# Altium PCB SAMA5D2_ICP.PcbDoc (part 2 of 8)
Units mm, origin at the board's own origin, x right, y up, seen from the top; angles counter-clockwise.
Board outline 150 x 100 mm, 6 copper layers (L1 - TOP, L2 - GND, L3 - SIG, L4 - SIG, L5 - VCC, L6 - BOT), stack 1.512 mm thick; 708 components, 597 nets, 2710 pads, 1437 vias.
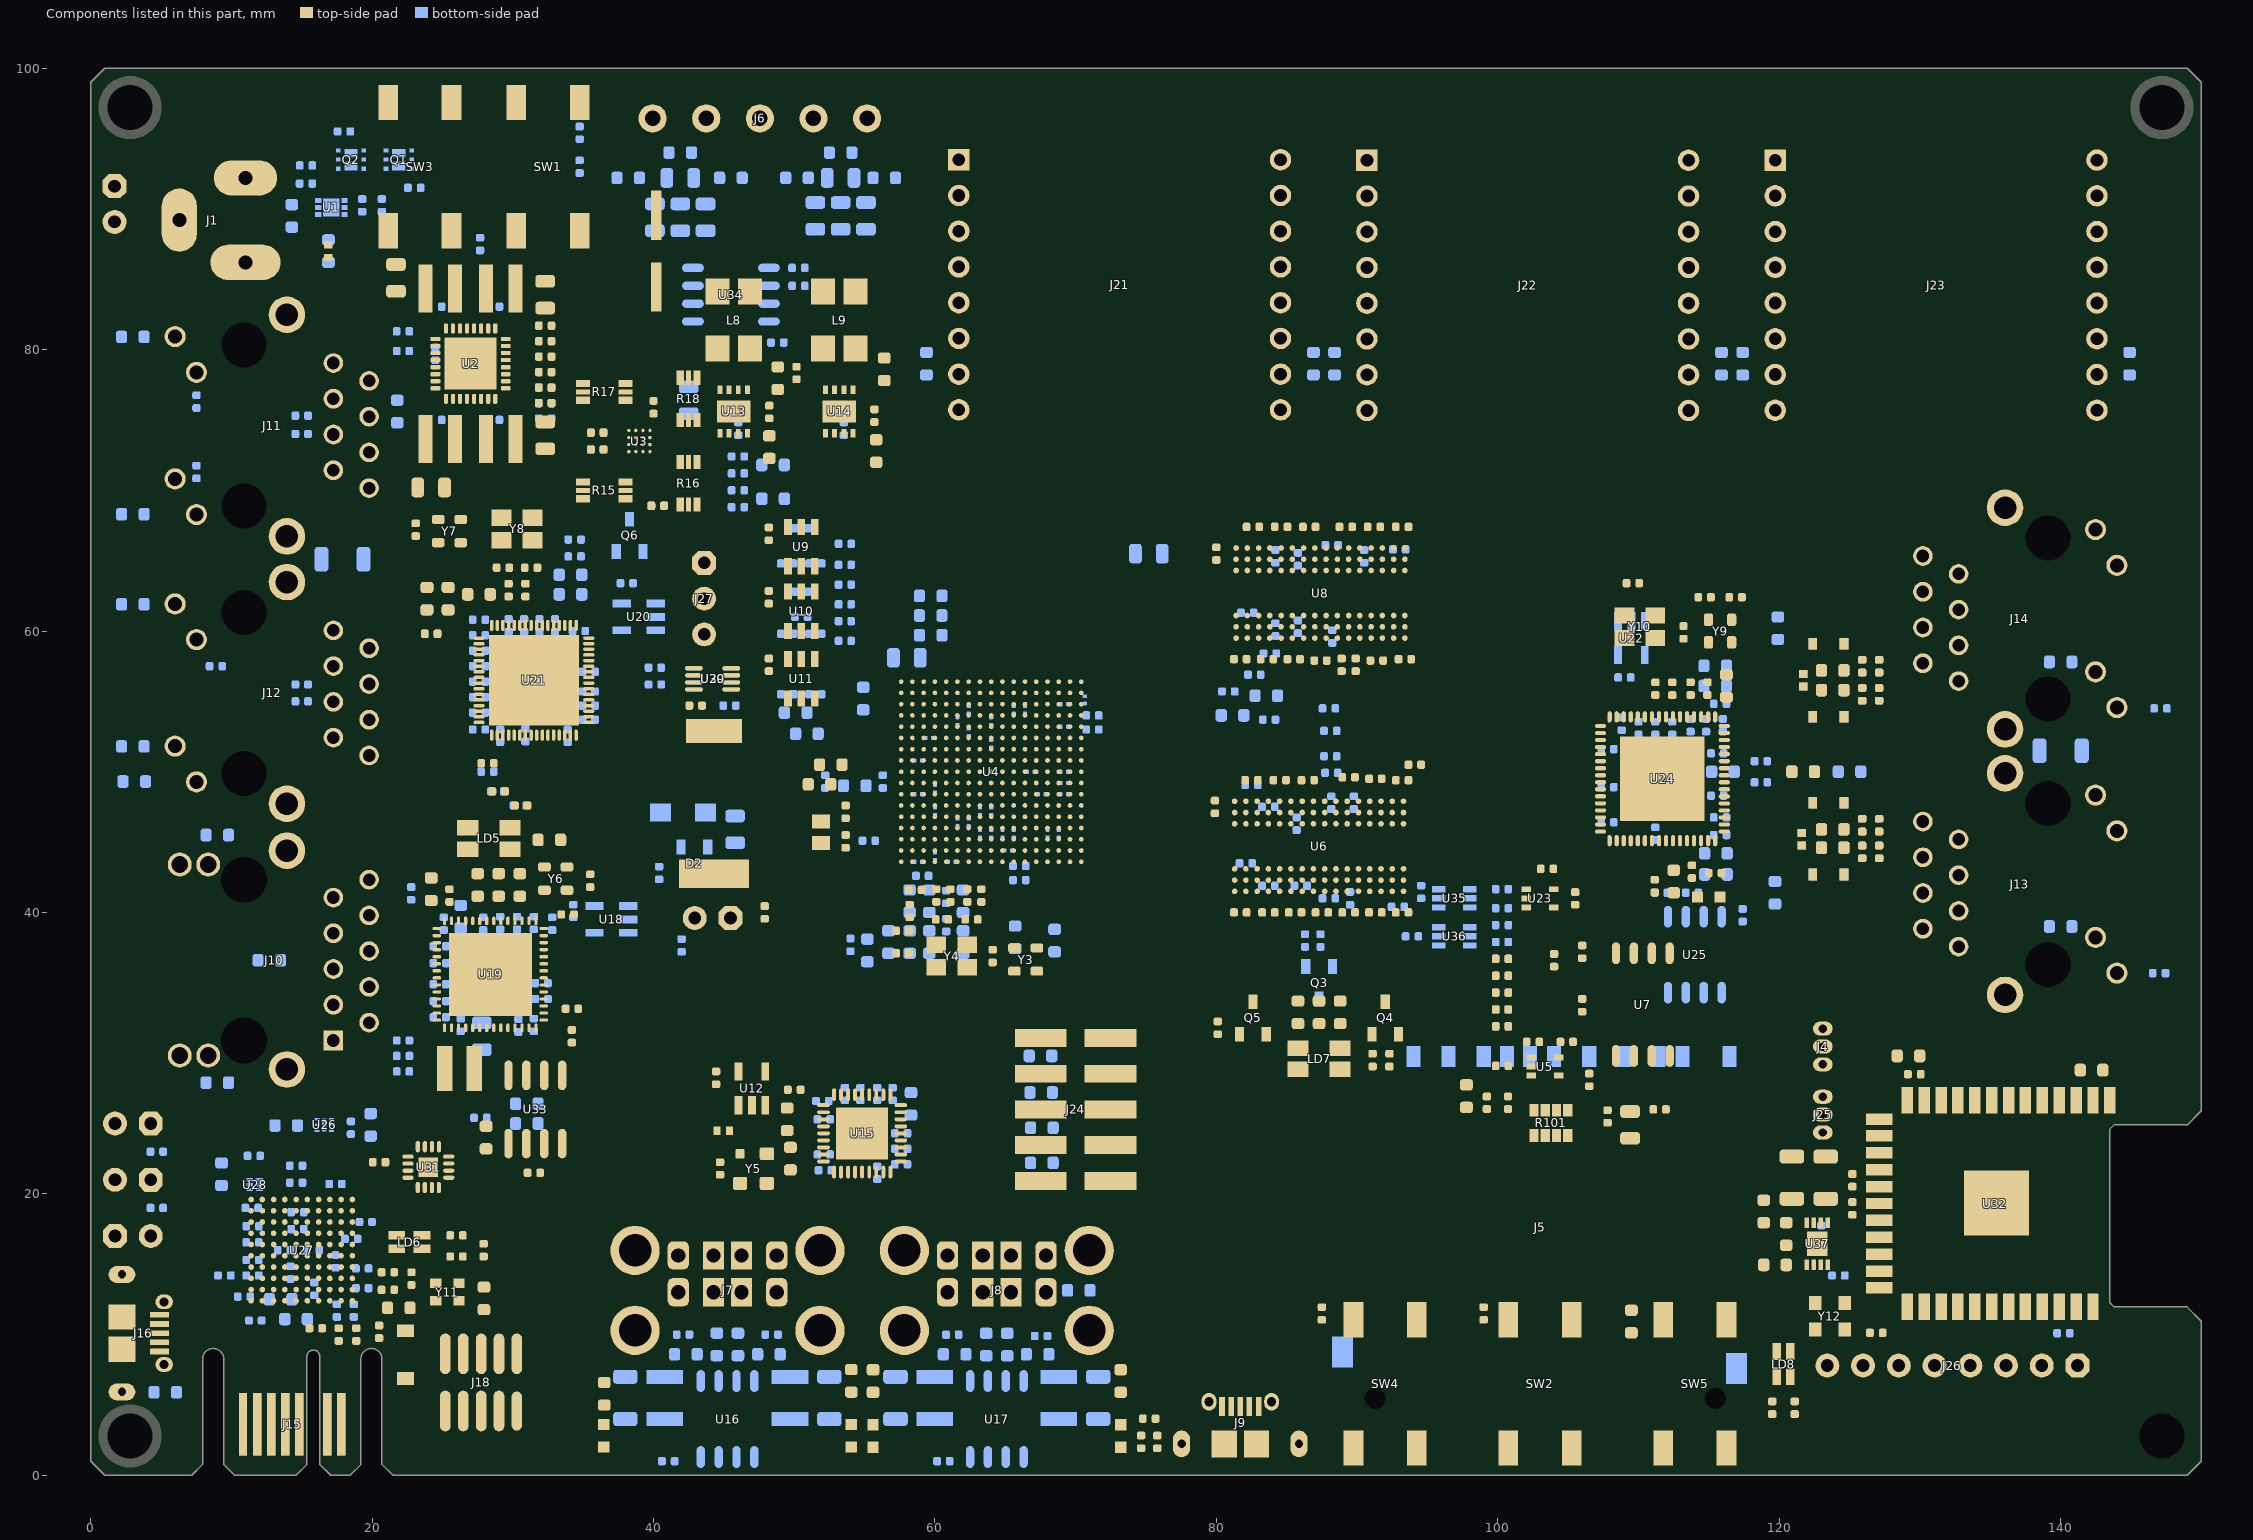
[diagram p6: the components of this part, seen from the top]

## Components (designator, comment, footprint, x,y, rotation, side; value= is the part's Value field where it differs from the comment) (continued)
R191 "Resistor" RES_C_0603 123.8,55.8 r180 top value=0R
R192 "Resistor" RES_C_0603 123.8,57.2 r180 top value=0R
R193 "Resistor" RES_C_0402 127.1,55.5 r270 bottom value=49.9R
R194 "Resistor" RES_C_0402 127.1,44.3 r270 top value=49.9R
R195 "Resistor" RES_C_0402 127.1,57.5 r90 bottom value=49.9R
R197 "Resistor" RES_C_0402 127.1,55.5 r270 top value=49.9R
R198 "Resistor" RES_C_1206 140,51.5 r180 bottom value=0R
R199 "Resistor" RES_C_0402 18.875,10 r270 top value=10k
R200 "Resistor" RES_C_0402 16,10.45 r180 top value=100R
R201 "Resistor" RES_C_0402 17.625,10 r90 top value=100R
R202 "Resistor" RES_C_0603 21.9,11.9 r180 top value=51R
R203 "Resistor" RES_C_0402 19.3,14.7 r0 bottom value=39R
R204 "Resistor" RES_C_0402 19.3,13.3 r0 bottom value=39R
R205 "Resistor" RES_C_0402 11.5,14.2 r0 bottom value=0R
R206 "Resistor" RES_C_0402 21.125,13.175 r180 top value=6.8k
R207 "Resistor" RES_C_0402 11.5,15.3 r0 bottom value=100k
R208 "Resistor" RES_C_0402 27.925,16 r270 top value=10k
R209 "Resistor" RES_C_0603 27.95,12.575 r90 top value=0R
R210 "Resistor" RES_C_0402 25.21,9 r90 bottom value=100R
R211 "Resistor" RES_C_0402 30.265,4.9 r270 bottom value=100k
R212 "Resistor" RES_C_0402 28.99,4.9 r270 bottom value=100k
R213 "Resistor" RES_C_0402 26.44,4.9 r270 bottom value=100k
R214 "Resistor" RES_C_0402 11.45,19 r0 bottom value=220R
R215 "Resistor" RES_C_0402 11.5,17.7 r0 bottom value=150R
R216 "Resistor" RES_C_0603 9.3,21.4 r270 bottom value=1k
R217 "Resistor" RES_C_0402 4.7,23 r0 bottom value=10k
R218 "Resistor" RES_C_0402 26,17.05 r0 top value=100R
R219 "Resistor" RES_C_0402 22.8,13.975 r270 top value=100R
R220 "Resistor" RES_C_0402 4.7,19 r0 bottom value=10k
R221 "Resistor" RES_C_0402 14.7,18.7 r0 bottom value=150R
R222 "Resistor" RES_C_0402 14.6,22 r0 bottom value=150R
R223 "Resistor" RES_C_0402 14.6,20.8 r180 bottom value=150R
R224 "Resistor" RES_C_0603 67.6,20.8 r0 bottom value=330R
R225 "Resistor" RES_C_0603 67.6,23.5 r0 bottom value=330R
R226 "Resistor" RES_C_0603 67.55,26 r0 bottom value=330R
R227 "Resistor" RES_C_0603 67.55,28.5 r180 bottom value=0R
R228 "Resistor" RES_C_0603 67.5,31.1 r180 bottom value=0R
R229 "Resistor" RES_C_0603 59.4,79 r270 bottom value=0R
R230 "Resistor" RES_C_0603 88.4,79 r270 bottom value=0R
R231 "Resistor" RES_C_0603 117.4,79 r270 bottom value=0R
R232 "Resistor" RES_C_0603 67.6,22.2 r180 bottom value=330R
R233 "Resistor" RES_C_0603 67.6,24.7 r180 bottom value=330R
R234 "Resistor" RES_C_0603 67.55,27.2 r180 bottom value=0R
R235 "Resistor" RES_C_0603 67.5,29.8 r0 bottom value=0R
R236 "Resistor" RES_C_0603 86.9,79 r270 bottom value=0R
R237 "Resistor" RES_C_0603 115.9,79 r270 bottom value=0R
R238 "Resistor" RES_C_0603 144.9,79 r270 bottom value=0R
R239 "Resistor" RES_C_0402 86.3,38 r270 bottom value=100R
R240 "Resistor" RES_C_0402 91.1,29.5 r90 top value=100R
R241 "Resistor" RES_C_0402 80.1,31.8 r270 top value=100R
R242 "Resistor" RES_C_0402 87.4,38 r90 bottom value=10k
R243 "Resistor" RES_C_0402 92.3,29.5 r270 top value=10k
R244 "Resistor" RES_C_0603 87.3,32.9 r270 top value=1k
R245 "Resistor" RES_C_0603 88.8,32.9 r270 top value=1k
R246 "Resistor" RES_C_0603 85.8,32.9 r270 top value=2.2k
R247 "Resistor" RES_C_0402 125.2,18.965 r90 top value=100k
R248 "Resistor" RES_C_0603 142.2,28.8 r0 top value=0R
R249 "Resistor" RES_C_0402 140.2,10.1 r0 bottom value=10k
R250 "Resistor" RES_C_0402 34.75,93 r90 bottom value=100R
R251 "Resistor" RES_C_0402 99,11.5 r270 top value=100R
R252 "Resistor" RES_C_0402 27.675,87.5 r90 bottom value=100R
R254 "Resistor" RES_C_0402 87.5,11.5 r270 top value=100R
R255 "Resistor" RES_C_0603 109.5,10.925 r90 top value=0R
R256 "Resistor" RES_C_0402 34.75,95.4 r90 bottom value=10k
R257 "Resistor" RES_C_0402 121.1,4.8 r270 top value=100R
R258 "Resistor" RES_C_0402 119.5,4.8 r270 top value=100R
R259 "Resistor" RES_C_0402 30.5,47.6 r180 bottom value=4.7k
R260 "Resistor" RES_C_0402 127.1,57.5 r90 top value=49.9R
R261 "Resistor" RES_C_0402 147,35.69 r180 bottom value=10k
R262 "Resistor" RES_C_0402 147.1,54.5 r180 bottom value=10k
R263 "Resistor" RES_C_0402 7.52,71.3 r90 bottom value=10k
R264 "Resistor" RES_C_0402 7.52,76.3 r270 bottom value=10k
R265 "Resistor" RES_C_0402 8.9,57.5 r0 bottom value=10k
R266 "Resistor" RES_C_0402 28.2,50.6 r180 top value=4.7k
R267 "Resistor" RES_C_0402 30.6,47.6 r180 top value=4.7k
R268 "Resistor" RES_C_0402 42,37.65 r270 bottom value=10k
R269 "Resistor" RES_C_0402 50.3,85.805 r180 bottom value=22R
R270 "Resistor" RES_C_0402 50.3,84.535 r180 bottom value=22R
R271 "Resistor" RES_C_0402 124.2,14.2 r180 bottom value=10k
SW1 "Switch 4 Pin" SW_SMD_6mmX6mm_TL3301 32.5,93 r270 top locked value="TACT SPST"
SW2 "Switch 4 Pin" SW_SMD_6mmX6mm_TL3301 103,6.5 r90 top value="TACT SPST"
SW3 "Switch 4 Pin" SW_SMD_6mmX6mm_TL3301 23.4,93 r270 top locked value="TACT SPST"
SW4 "Switch 4 Pin" SW_SMD_6mmX6mm_TL3301 92,6.5 r90 top value="TACT SPST"
SW5 "Switch 4 Pin" SW_SMD_6mmX6mm_TL3301 114,6.5 r90 top value="TACT SPST"
U1 "NCP349 DFN-6" DFN-6_2x1.6_EP0.4x0.35 17.1,90.1 r90 bottom value=NCP349MNAETBG
U2 "MCP16502AA" QFN-32_5X5_EP3.7X3.7 27,79 r0 top
U3 "PAC1934 WLCSP-16" WLCSP-16_2.215X2.16 39,73.5 r180 top value=PAC1934
U4 "ATSAMA5D27C LFBGA-289" LFBGA-289_P0.8_14x14x1.4 64,50 r0 top locked value=ATSAMA5D27C
U5 "NL17SZ126-D SOT-353" SOT-353 103.355,29.05 r270 top value=NL17SZ126-D
U6 "W632GU6MB" TFBGA-96_13X7.5 87.3,44.7 r90 top locked value=W632GU6MB-12
U7 "SST26VFXXX SOIC-8_WSON-8_SOIJ-8" SOIJ-8 110.305,33.45 r90 top value=SST26VF064B
U8 "W632GU6MB" TFBGA-96_13X7.5 87.4,62.7 r90 top locked value=W632GU6MB-12
U9 "24XXXX SOT-23-6" SOT-23-6 50.5,66 r0 top value=24AA025E48
U10 "24XXXX SOT-23-6" SOT-23-6 50.5,61.4 r0 top value=24AA025E48
U11 "24XXXX SOT-23-6" SOT-23-6 50.5,56.6 r0 top value=24AA025E48
U12 "74XX1G08_9 SOT-23-5" SOT-23-5 46.995,27.5 r0 top value=SN74LVC1G08DBVR
U13 "MCP2542 DFN-8" DFN-8_3x3_EP2.4X1.55 45.7,75.6 r0 top value=MCP2542
U14 "MCP2542 DFN-8" DFN-8_3x3_EP2.4X1.55 53.2,75.6 r0 top value=MCP2542
U15 "USB2534 SQFN-36" QFN-36_6x6_EP3.7x3.7 54.83,24.3 r90 top locked value=USB2534I-1080AEN
U16 "MIC2026-2076 DIP-8 SOIC-8" SOIC-8 45.265,4 r90 bottom value=MIC2026-1YM
U17 "MIC2026-2076 DIP-8 SOIC-8" SOIC-8 64.4,4 r90 bottom value=MIC2026-1YM
U18 "74XX1G08_9 SOT-23-5" SOT-23-5 37,39.5 r270 bottom value=SN74LVC1G08DBVR
U19 "LAN7850 QFN-56" QFN-56_8X8_EP5.9X5.9 28.4,35.6 r0 top value=LAN7850T
U20 "74XX1G08_9 SOT-23-5" SOT-23-5 38.95,61 r270 bottom value=SN74LVC1G08DBVR
U21 "KSZ8563RNX" QFN-64_8X8-EP6.5SQ 31.5,56.5 r0 top locked
U22 "74XX1G08_9 SOT-23-5" SOT-23-5 109.5,59.5 r0 bottom value=SN74LVC1G08DBVR
U23 "NL17SZ125-D SOT-353" SOT-353 103,41 r270 top value=NL17SZ125-D
U24 "LAN9252 QFN-64" QFN-64_9X9_EP6 111.7,49.5 r270 top locked value=LAN9252I/ML
U25 "24XX01_02_04_08_16_32_64_128_256_512_1025 SOIC-8_SOIJ-8_TSSOP-8_PDIP-8_MSOP-8" SOIC-8 114,37 r90 bottom value=24FC512
U26 "MIC5528MT DFN-6" DFN-6_1.2x1.2 16.6,24.9 r270 bottom value="MIC5528 3V3"
U27 "ATSAM3U4CA-CU TFBGA-100" TFBGA-100_P0.8_9X9X1.1 15,16 r180 top value=ATSAM3U4CA-CU
U28 "NLAS3157 ULLGA-6" ULLGA-6_1X1 11.65,20.65 r270 bottom value=NLAS3157MX3TC
U29 "NL27WZ125 US-8" US-8 44.2,56.6 r0 bottom value=NL27WZ125USG
U30 "NL27WZ126 US-8" US-8 44.2,56.6 r180 top value=NL27WZ126USG
U31 "NLAS3899B QFN16" QFN-16_3X3_EP1.4X1.4 24,21.9 r90 top value=NLAS3899B
U32 "MODULE ATWILC3000-MR110CA" "MODULE ATWILC3000-MR110CA" 135.45,19.345 r270 top value=ATWILC3000-MR110CA
U33 "93XX66A_B_C PDIP-8_SOIC-8_TSSOP-8_MSOP-8" SOIC-8_150MIL 31.6,26 r270 top value=93AA66A
U34 "ATECC608A-SSHDA-B SOIC-8" SOIC-8 45.5,83.9 r0 bottom value=ATECC608A-SSHDA
U35 "74LVC1G3157 SOT-23-6_SC-70-6" SC-70-6 96.896,41 r270 bottom value=74LVC1G3157
U36 "74LVC1G3157 SOT-23-6_SC-70-6" SC-70-6 96.9,38.3 r270 bottom value=74LVC1G3157
U37 "MCP172X FIX DFN-8" DFN-8_2x3 122.7,16.45 r0 top value=MCP1725/3.3V
Y1 "Crystal 2 Pins" CRYSTAL_NX2012SA 51.9,45.7 r270 top value=32.768kHz
Y3 "DSC10xx DFN-4" DFN-4_2.5x2 66.446,36.652 r90 top value=12MHz
Y4 "Crystal 4 pins 1-3" CRYSTAL_TSX-3225_L3.2W2.5H0.6 61.2,36.9 r180 top value=12Mhz
Y5 "DSC10xx DFN-4" CDFN-4_3.2X2.5 47.103,21.796 r0 top value=24MHz
Y6 "DSC10xx DFN-4" DFN-4_2.5x2 33.05,42.405 r90 top value=25MHz
Y7 "DSC10xx DFN-4" DFN-4_2.5x2 25.5,67.1 r270 top value=25MHz
Y8 "Crystal 4 pins 1-3" CRYSTAL_L3.2W2.5H0.8 30.3,67.25 r0 top value=25MHz
Y9 "DSC10xx DFN-4" DFN-4_2.5x2 115.8,60 r180 top value=25MHz
Y10 "Crystal 4 pins 1-3" CRYSTAL_L3.2W2.5H0.8 110.1,60.3 r180 top value=25MHz
Y11 "OSCILLATOR DSC60XX" OSCILLATOR_DSC60000L2.5W2.0H0.89 25.35,13.025 r180 top value="12.00 MHz"
Y12 "OSC_DSC6083CE2A_3225" OSCILLATOR_DSC1001_L3.2W2.5H0.85 123.6,11.3 r180 top value=32.768Hz

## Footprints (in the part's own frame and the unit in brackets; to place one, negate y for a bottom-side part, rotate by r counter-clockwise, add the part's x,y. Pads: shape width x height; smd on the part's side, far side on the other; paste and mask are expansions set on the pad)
10067847-001RLF [mm]
  rect 1x1.5 smd: 1(6.475,12.15) 2(3.975,12.15) 3(0.675,12.15) 4(-1.025,12.15) 5(-3.525,12.15) 6(-6.025,12.15) 7(-8.45,12.15) 8(-10.15,12.15) 9(8.975,12.15) 10(2.325,12.15) 11(-13.5,12.15)
  round 0 hole 1.5 unplated mask+0.05: 1.5mm(-12.5,-12.15) 1.5mm(11.7,-12.15)
  rect 1.5x2.2 smd: 12(-14,-10.05) 12(14,-8.85)
  L1 - TOP keep-out region: 8.425,3.05 9.525,3.05 9.525,1.05 8.425,1.05
  L1 - TOP keep-out region: 0.55,5.25 2.45,5.25 2.45,2.75 0.55,2.75
  L1 - TOP keep-out region: 5.925,6.05 7.025,6.05 7.025,3.55 5.925,3.55
  L1 - TOP keep-out region: 3.425,5.25 4.525,5.25 4.525,3.25 3.425,3.25
  L1 - TOP keep-out region: -1.575,4.75 -0.475,4.75 -0.475,2.75 -1.575,2.75
  L1 - TOP keep-out region: -4.075,5.15 -2.975,5.15 -2.975,3.15 -4.075,3.15
  L1 - TOP keep-out region: -6.575,5.15 -5.475,5.15 -5.475,3.15 -6.575,3.15
  L1 - TOP keep-out region: -15.1,2.35 -13.9,2.35 -13.9,-3.95 -15.1,-3.95
  L1 - TOP keep-out region: -9,5.15 -7.9,5.15 -7.9,3.15 -9,3.15
  L1 - TOP keep-out region: -10.7,5.15 -9.6,5.15 -9.6,3.15 -10.7,3.15
  silkscreen extent -15,-17.85 15,13.15, body extent -14.23,-17.65 14.22,12.6, height 2.9
CAP_AL_D8 [mm]
  rect 3.5x0.75 smd: 1(-2.55,0) 2(2.55,0)
  silkscreen extent -3.43,-3.3 3.43,3.3, body extent -3.5,-3.3 3.5,3.3, height 7.7
CAP_C_0201 [mm] "Chip Capacitor, 2-Leads, Body 0.6x0.3mm, IPC Medium Density"
  rrect50% 0.275x0.3 smd mask+0.064: 1(-0.262,0) 2(0.262,0)
  body extent -0.3,-0.15 0.3,0.15, height 0.28
CAP_C_0402 [mm] "Chip Capacitor, 2-Leads, Body 1.0x0.5mm, IPC High Density"
  rrect50% 0.55x0.6 smd: 1(-0.45,0) 2(0.45,0)
  body extent -0.5,-0.3 0.5,0.3, height 0.2
CAP_C_0603 [mm] "Chip Capacitor, 2-Leads, Body 1.6x0.8mm, IPC Medium Density"
  rrect50% 0.8x0.9 smd: 1(-0.8,0) 2(0.8,0)
  silkscreen extent -0.1,-0.38 0.1,0.38, body extent -0.8,-0.4 0.8,0.4, height 0.3
CAP_C_0805 [mm] "Chip Capacitor, 2-Leads, Body 2.0x1.3mm, IPC Medium Density"
  rrect50% 0.9x1.4 smd: 1(-0.95,0) 2(0.95,0)
  silkscreen extent -0.2,-0.7 0.2,0.7, body extent -1,-0.62 1,0.63, height 0.78
CAP_C_1206 [mm] "Chip Capacitor, 2-Leads, Body 3.2x1.6mm, IPC Medium Density"
  rrect50% 1x1.75 smd: 1(-1.5,0) 2(1.5,0)
  silkscreen extent -0.6,-0.77 0.6,0.77, body extent -1.6,-0.8 1.6,0.8, height 1
CAP_C_1210 [mm] "Chip Capacitor, 2-Leads, Body 3.2x2.5mm, IPC Medium Density"
  rect 1x2.6 smd: 1(-1.5,0) 2(1.5,0)
  silkscreen extent -0.6,-1.2 0.6,1.2, body extent -1.6,-1.25 1.6,1.25, height 0.95
CAP_SMD_ECH-U1C471JX5 [mm]
  rect 5x2 smd: 1(0,5.15)
  rect 4x1.7 smd: 2(0,-5)
  silkscreen extent -3.5,-3.62 4.05,5.51, body extent -3.4,-5.29 3.4,5.7, height 1.57
CDFN-4_3.2X2.5 [mil] "Oscillator DSC60X1C"
  rrect30% 26x26 smd: 1(-37.5,41.5)
  rrect30% 40x36 smd paste-2: 2(-37.5,-41.5) 3(37.5,-41.5) 4(37.5,41.5)
  L1 - TOP region: -53.5,23.5 -55.03,23.8 -56.33,24.67 -57.2,25.97 -57.5,27.5 -57.5,27.5 -57.5,55.5 -57.2,57.03 -56.33,58.33 -55.03,59.2 -53.5,59.5 -53.5,59.5 -27.5,59.5 -17.5,49.5 -17.5,27.5 -17.8,25.97 -18.67,24.67 -19.97,23.8 -21.5,23.5 -21.5,23.5
  silkscreen extent -68,-73 68,73, body extent -49,-63 49,63, height 34
CON_EDGE-CARD_PCB_RA_MEC1-108-02-F-D-RA1-SL [mm] "connector matching PCB pads"
  rect 0.6x4.45 smd far side paste-1 mask+0.05: 1(0,0) 3(-1,0) 7(-3,0) 9(-4,0) 11(-5,0) 13(-6,0) 15(-7,0)
  rect 0.6x4.45 smd paste-1 mask+0.05: 2(0,0) 4(-1,0) 8(-3,0) 10(-4,0) 12(-5,0) 14(-6,0) 16(-7,0)
  Keep-Out Layer lines w0.05: -10.645,-3.625 -9.87,-2.85 -9.87,4.64 cw(c-9.12,4.64) -8.37,4.64 -8.37,-2.85 -7.595,-3.625 -3.227,-3.625 -2.452,-2.85 -2.452,4.818 cw(c-1.995,4.818) -1.538,4.818 -1.538,-2.85 -0.763,-3.625 0.605,-3.625 1.38,-2.85 1.38,4.64 cw(c2.13,4.64) 2.88,4.64 2.88,-2.85 3.655,-3.625
  body extent -7.3,-2.22 0.3,2.23, height 0.02
CON_JACK_POWER_TH_RA_MPD_EJ508A [mm] "CONN POWER JACK MALE 2.1MM CLSD"
  oval 2.5x5 hole 1 slot 3.5 at 90 deg: 1(3,0)
  oval 2.5x4.5 hole 1 slot 3 at 90 deg: 2(-3,0)
  oval 4.5x2.5 hole 1 slot 3 at 0 deg: 3(0,-4.7)
  silkscreen extent -10.8,-4.5 3.7,4.5, body extent -10.7,-4.9 3.7,4.5, height 11.1
CON_RJ-45_TH_RA_PULSE_JD1-0001NL [mm] "J00-0061NL_RJ45_connector"
  round 2.6 / inner round 1.524 / far side round 2.6 hole 1.6: 0(-7.775,3.05) 0(7.775,3.05)
  rect 1.4x1.4 hole 0.9: 1(5.715,6.35)
  round 1.4 hole 0.9: 2(4.445,8.89) 3(3.175,6.35) 4(1.905,8.89) 5(0.635,6.35) 6(-0.635,8.89) 7(-1.905,6.35) 8(-3.175,8.89) 9(-4.445,6.35) 10(-5.715,8.89)
  round 0 hole 3.25 unplated mask+0.05: 3.25mm(-5.715,0) 3.25mm(5.715,0)
  round 1.7 hole 1.2: 11(6.785,-2.54) 12(6.785,-4.57) 13(-6.785,-2.54) 14(-6.785,-4.57)
  silkscreen extent -8.51,-11.3 8.51,11.05, body extent -9.88,-11.32 9.87,10.93, height 16
CON_TERMINAL_3.81_1x5_TH_RA_PHO_1727049 [mm]
  round 2 hole 1.1: 1(-7.62,0) 2(-3.81,0) 3(0,0) 4(3.81,0) 5(7.62,0)
  silkscreen extent -9.91,-4.06 9.91,3.94, body extent -9.53,-3.74 9.52,3.56, height 8.5
CON_USB2.0-A_Dual_RCPT_TH_RA_AMN_AU-Y1008-2 [mm] "CONN USB 2.0 A DUAL RCPT TH R/A L=17.5mm, W=14.5mm, H=15.7mm"
  round 3.5 hole 2.3: 0(-6.57,-2.84) 0(-6.57,2.84) 0(6.57,-2.84) 0(6.57,2.84)
  rrect50% 1.5x2 hole 1: 1(-3.5,2.49) 4(3.5,2.49) 5(-3.5,-0.13) 8(3.5,-0.13)
  rect 1.5x2 hole 1: 2(-1,2.49) 3(1,2.49) 6(-1,-0.13) 7(1,-0.13)
  silkscreen extent -6.8,-13.34 6.8,4.56, body extent -7.85,-13.74 7.85,3.86, height 16.2
CON_USB_Micro-AB_SMD_RA_MOLEX_0475890001 [mm] "Connector, Receptacle, Micro-USB Type AB, R/A, SMT"
  oval 1.225x1.9 hole 0.6 slot 1.3 at 90 deg: 0(-4.175,0.127) 0(4.175,0.127)
  oval 1.05x1.25 hole 0.65 slot 0.85 at 90 deg mask+0.05: 0(-2.225,3.125) 0(2.225,3.125)
  rect 1.8x1.9 smd: 0(-1.15,0.127) 0(1.15,0.127)
  rect 0.4x1.35 smd mask+0.05: 1(-1.3,2.8) 2(-0.65,2.8) 3(0,2.8) 4(0.65,2.8) 5(1.3,2.8)
  L1 - TOP region: 4.65,1.077 2.6,1.077 2.6,-0.823 4.65,-0.823
  L1 - TOP region: -4.675,-0.823 -2.6,-0.823 -2.6,1.077 -4.675,1.077
  silkscreen extent -3.85,-2.12 3.85,2.15, body extent -4.32,-2.57 4.33,3.33, height 2.76
CRYSTAL_L3.2W2.5H0.8 [mm] "L=3.2mm, W=2.5mm, H=0.8mm"
  rect 1.4x1.15 smd: 1(-1.1,-0.8) 2(1.1,-0.8) 3(1.1,0.8) 4(-1.1,0.8)
  silkscreen extent -2.1,-1.68 2.1,1.68, body extent -1.6,-1.25 1.6,1.25, height 0.8
CRYSTAL_NX2012SA [mil] "Crystal NDK NX2012SA"
  rect 40x50 smd paste-1: 1(-30,0) 2(30,0)
  silkscreen extent -64,-39 64,39, body extent -40,-20 40,20, height 21
CRYSTAL_TSX-3225_L3.2W2.5H0.6 [mm] "Epson L=3.2mm, W=2.5mm, H=0.6mm"
  rect 1.4x1.15 smd: 1(-1.1,-0.8) 2(1.1,-0.8) 3(1.1,0.8) 4(-1.1,0.8)
  silkscreen extent -2.1,-1.68 2.1,1.68, body extent -1.6,-1.25 1.6,1.25, height 0.77
DFN-4_2.5x2 [mm] "Oscillator DSC1121"
  rrect50% 0.65x0.9 smd: 1(-0.825,-0.8) 2(0.825,-0.8) 3(0.825,0.8) 4(-0.825,0.8)
  silkscreen extent -1.5,-1.55 1.5,1.55, body extent -1.25,-1 1.25,1, height 0.86
DFN-6_1.2x1.2 [mm] "DFN, 6-Leads, Body 1.2x1.2mm (max), Pitch 0.65"
  rect 0.18x0.35 smd: 1(-0.4,-0.525) 2(0,-0.525) 3(0.4,-0.525) 4(0.4,0.525) 5(0,0.525) 6(-0.4,0.525)
  rect 0.94x0.3 smd: 7(0,0)
  silkscreen extent -1,-0.4 1,0.4, body extent -0.62,-0.62 0.63,0.63, height 0.6
DFN-6_2x1.6_EP0.4x0.35 [mm] "DFN, 6-Leads, Body 2x1.6mm (max), Pitch 0.5"
  rect 0.36x0.43 smd mask+0.038: 1(-0.5,-0.925) 2(0,-0.925) 3(0.5,-0.925) 4(0.5,0.925) 5(0,0.925) 6(-0.5,0.925)
  rect 1.3x1.15 smd mask+0.038: 7(0,0)
  silkscreen extent -0.95,-0.4 0.95,0.4, body extent -0.8,-1 0.8,1, height 1
DFN-8_2x3 [mm] "DFN, 8-Leads, Body 3.0x2.0mm (max), Pitch 0.5"
  rect 0.3x0.75 smd mask+0.05: 1(-0.75,-1.5) 2(-0.25,-1.5) 3(0.25,-1.5) 4(0.75,-1.5) 5(0.75,1.5) 6(0.25,1.5) 7(-0.25,1.5) 8(-0.75,1.5)
  rect 1.45x1.75 smd mask+0.075: 9(0,0)
  silkscreen extent -1.1,-0.8 1.1,0.8, body extent -1,-1.5 1,1.5, height 1
DFN-8_3x3_EP2.4X1.55 [mm] "DFN, 8-Leads, Body 3.0x3.0mm (max), Pitch 0.65mm, IPC Medium Density"
  rect 0.35x0.6 smd: 1(-0.975,-1.55) 2(-0.325,-1.55) 3(0.325,-1.55) 4(0.975,-1.55) 5(0.975,1.55) 6(0.325,1.55) 7(-0.325,1.55) 8(-0.975,1.55)
  rect 2.4x1.55 smd: 9(0,0)
  silkscreen extent -1.6,-1.5 1.6,1.5, body extent -1.5,-1.5 1.5,1.5, height 0.61
DIO_C_0402 [mm]
  rect 0.55x0.6 smd: 1(-0.45,0) 2(0.45,0)
  body extent -0.5,-0.3 0.5,0.3, height 0.5
HDR_M_1.27_1x3 [mm] "Header Male Vertical 3 Way 1.27mm Pitch"
  oval 1x1.4 hole 0.6: 1(-1.27,0) 2(0,0) 3(1.27,0)
  silkscreen extent -2.13,-1.4 2.16,1.4, body extent -1.9,-1.22 1.91,1.22, height 8.38
HDR_M_1.27_2x5_SMD_V_SAM_FTSH-105-01-F-DV-K [mil]
  oval 30x114 smd: 1(-100,-80) 3(-50,-80) 4(-50,80) 5(0,-80) 6(0,80) 7(50,-80) 8(50,80) 9(100,-80) 10(100,80)
  oval 29.13x109.84 smd: 2(-100,80)
  silkscreen extent -138,-157 134,75, body extent -125,-115 125,115, height 241
HDR_M_2.54_1x2 [mm] "Header Male Vertical 4 Way 2.54mm Pitch"
  oct 1.7x1.7 hole 0.9: 1(-1.27,0)
  round 1.7 hole 0.9: 2(1.27,0)
  silkscreen extent -2.6,-1.35 2.6,1.4, body extent -2.54,-1.27 2.54,1.27, height 5.94
HDR_M_2.54_1x3 [mm] "Header Male Vertical 4 Way P=2.54mm"
  oct 1.7x1.7 hole 0.9: 1(-2.54,0)
  round 1.7 hole 0.9: 2(0,0) 3(2.54,0)
  silkscreen extent -3.94,-1.4 3.96,1.4, body extent -3.8,-1.26 3.82,1.28, height 5.94
HDR_M_2.54_1x8 [mm] "Header Male Vertical 8 Way 2.54mm Pitch"
  oct 1.7x1.7 hole 0.9: 1(-8.89,0)
  round 1.7 hole 0.9: 2(-6.35,0) 3(-3.81,0) 4(-1.27,0) 5(1.27,0) 6(3.81,0) 7(6.35,0) 8(8.89,0)
  silkscreen extent -10.29,-1.4 10.29,1.4, body extent -10.16,-1.27 10.16,1.27, height 5.94
HDR_M_2.54_2x5_SMD_SAM_TSM-105-01-T-DV [mm]
  rect 1.27x3.68 smd: 1(-5.08,-2.48) 2(-5.08,2.48) 3(-2.54,-2.48) 4(-2.54,2.48) 5(0,-2.48) 6(0,2.48) 7(2.54,-2.48) 8(2.54,2.48) 9(5.08,-2.48) 10(5.08,2.48)
  silkscreen extent -6.35,-4.63 6.35,4.62, body extent -6.35,-3.85 6.35,3.85, height 9.65
IND_C_0603 [mm] "Chip Inductor, 2-Leads, Body 1.6x0.8mm, IPC Medium Density"
  rrect50% 0.8x0.9 smd: 1(-0.8,0) 2(0.8,0)
  silkscreen extent -0.1,-0.35 0.1,0.35, body extent -0.8,-0.4 0.8,0.4, height 0.95
IND_C_1212 [mm] "FIXED IND 1.5UH 4.19A 67 MOHM"
  rect 1x3.4 smd: 1(-1.05,0) 2(1.05,0)
  silkscreen extent -1.9,-2 1.9,2, body extent -1.5,-1.5 1.5,1.5, height 1.2
IND_EP_SIMDAD_1812 [mm] "Inductor Choke EPCOS SIMDAD 1812 Series Size L 5.2x12.5mm W 3.2mm"
  rect 1.7x1.85 smd: L1(-1.15,2.025) L1'(-1.15,-2.025) L2(1.15,2.025) L2'(1.15,-2.025)
  silkscreen extent -2.1,-1 2.1,1, body extent -1.6,-2.25 1.6,2.25, height 3.24
IND_SRN3015TA [mm]
  rect 1.1x3.2 smd: 1(-1.05,0) 2(1.05,0)
  silkscreen extent -0.28,-1.63 0.28,1.63, body extent -1.5,-1.5 1.5,1.5, height 1.5
J00-0045NL_RJ45_CONNECTOR [mm] "J00-0061NL_RJ45_connector"
  round 1.4 / inner round 1.524 / far side round 1.4 hole 0.9: 1(-4.445,6.35) 2(-3.175,8.89) 3(-1.905,6.35) 4(-0.635,8.89) 5(0.635,6.35) 6(1.905,8.89) 7(3.175,6.35) 8(4.445,8.89)
  round 0 hole 3.2 unplated mask+0.05: 3.20mm(-5.715,0) 3.20mm(5.715,0)
  round 1.5 / inner round 1.524 / far side round 1.4 hole 1: 9(-6.325,-4.9) 10(-3.785,-3.38) 11(3.785,-4.9) 12(6.325,-3.38)
  round 2.6 / inner round 1.524 / far side round 2.6 hole 1.6: 13(-7.875,3.05) 14(7.875,3.05)
  silkscreen extent -8.51,-11.3 8.51,11.05, body extent -8.12,-10.9 8.12,10.77, height 13.74
LABEL_Need_Help_Small [mm] "Small Serial Number Assembly Label"
  silkscreen extent -11.43,-3.18 11.43,3.18, body extent -11.43,-3.18 11.43,3.18, height 0.3
LED_0402_RED [mm] "LED chip 0402"
  rect 0.5x0.6 smd: 1(-0.45,0) 2(0.45,0)
  silkscreen extent 1,-0.4 1,0.4, body extent -0.5,-0.3 0.5,0.3, height 0.2
LED_0603_GREEN [mm] "LED chip 0603"
  rect 0.8x0.8 smd: 1(-0.8,0) 2(0.8,0)
  silkscreen extent 1.5,-0.4 1.5,0.4, body extent -0.81,-0.4 0.81,0.4, height 0.6
LED_DUAL_SMD_2x1.25mm [mm] "LED 2X1.2MM RD/GN WTR CLR SMD"
  rect 1.2x0.6 smd: 1(0.9,0.475) 2(-0.9,0.475) 3(-0.9,-0.475) 4(0.9,-0.475)
  silkscreen extent -2.16,-1.07 1.8,1.07, body extent -0.81,-0.75 0.81,0.75, height 0.6
LFBGA-289_P0.8_14x14x1.4 [mm] "BGA, 289-Leads, Body 14.00x14.00mmx1.40mm, Pitch 0.80mm"
  round 0.33 smd: A1(-6.4,6.4) A2(-5.6,6.4) A3(-4.8,6.4) A4(-4,6.4) A5(-3.2,6.4) A6(-2.4,6.4) A7(-1.6,6.4) A8(-0.8,6.4) A9(0,6.4) A10(0.8,6.4) A11(1.6,6.4) A12(2.4,6.4) A13(3.2,6.4) A14(4,6.4) A15(4.8,6.4) A16(5.6,6.4) A17(6.4,6.4) B1(-6.4,5.6) B2(-5.6,5.6) B3(-4.8,5.6) B4(-4,5.6) B5(-3.2,5.6) B6(-2.4,5.6) B7(-1.6,5.6) B8(-0.8,5.6) B9(0,5.6) B10(0.8,5.6) B11(1.6,5.6) B12(2.4,5.6) B13(3.2,5.6) B14(4,5.6) B15(4.8,5.6) B16(5.6,5.6) B17(6.4,5.6) C1(-6.4,4.8) C2(-5.6,4.8) C3(-4.8,4.8) C4(-4,4.8) C5(-3.2,4.8) C6(-2.4,4.8) C7(-1.6,4.8) C8(-0.8,4.8) C9(0,4.8) C10(0.8,4.8) C11(1.6,4.8) C12(2.4,4.8) C13(3.2,4.8) C14(4,4.8) C15(4.8,4.8) C16(5.6,4.8) C17(6.4,4.8) D1(-6.4,4) D2(-5.6,4) D3(-4.8,4) D4(-4,4) D5(-3.2,4) D6(-2.4,4) D7(-1.6,4) D8(-0.8,4) D9(0,4) D10(0.8,4) D11(1.6,4) D12(2.4,4) D13(3.2,4) D14(4,4) D15(4.8,4) D16(5.6,4) D17(6.4,4) E1(-6.4,3.2) E2(-5.6,3.2) E3(-4.8,3.2) E4(-4,3.2) E5(-3.2,3.2) E6(-2.4,3.2) E7(-1.6,3.2) E8(-0.8,3.2) E9(0,3.2) E10(0.8,3.2) E11(1.6,3.2) E12(2.4,3.2) E13(3.2,3.2) E14(4,3.2) E15(4.8,3.2) E16(5.6,3.2) E17(6.4,3.2) F1(-6.4,2.4) F2(-5.6,2.4) F3(-4.8,2.4) F4(-4,2.4) F5(-3.2,2.4) F6(-2.4,2.4) F7(-1.6,2.4) F8(-0.8,2.4) F9(0,2.4) F10(0.8,2.4) F11(1.6,2.4) F12(2.4,2.4) F13(3.2,2.4) F14(4,2.4) F15(4.8,2.4) F16(5.6,2.4) F17(6.4,2.4) G1(-6.4,1.6) G2(-5.6,1.6) G3(-4.8,1.6) G4(-4,1.6) G5(-3.2,1.6) G6(-2.4,1.6) G7(-1.6,1.6) G8(-0.8,1.6) G9(0,1.6) G10(0.8,1.6) G11(1.6,1.6) G12(2.4,1.6) G13(3.2,1.6) G14(4,1.6) G15(4.8,1.6) G16(5.6,1.6) G17(6.4,1.6) H1(-6.4,0.8) H2(-5.6,0.8) H3(-4.8,0.8) H4(-4,0.8) H5(-3.2,0.8) H6(-2.4,0.8) H7(-1.6,0.8) H8(-0.8,0.8) H9(0,0.8) H10(0.8,0.8) H11(1.6,0.8) H12(2.4,0.8) H13(3.2,0.8) H14(4,0.8) H15(4.8,0.8) H16(5.6,0.8) H17(6.4,0.8) J1(-6.4,0) J2(-5.6,0) J3(-4.8,0) J4(-4,0) J5(-3.2,0) J6(-2.4,0) J7(-1.6,0) J8(-0.8,0) J9(0,0) J10(0.8,0) J11(1.6,0) J12(2.4,0) J13(3.2,0) J14(4,0) J15(4.8,0) J16(5.6,0) J17(6.4,0) K1(-6.4,-0.8) K2(-5.6,-0.8) K3(-4.8,-0.8) K4(-4,-0.8) K5(-3.2,-0.8) K6(-2.4,-0.8) K7(-1.6,-0.8) K8(-0.8,-0.8) K9(0,-0.8) K10(0.8,-0.8) K11(1.6,-0.8) K12(2.4,-0.8) K13(3.2,-0.8) K14(4,-0.8) K15(4.8,-0.8) K16(5.6,-0.8) K17(6.4,-0.8) L1(-6.4,-1.6) L2(-5.6,-1.6) L3(-4.8,-1.6) L4(-4,-1.6) L5(-3.2,-1.6) L6(-2.4,-1.6) L7(-1.6,-1.6) L8(-0.8,-1.6) L9(0,-1.6) L10(0.8,-1.6) L11(1.6,-1.6) L12(2.4,-1.6) L13(3.2,-1.6) L14(4,-1.6) L15(4.8,-1.6) L16(5.6,-1.6) L17(6.4,-1.6) M1(-6.4,-2.4) M2(-5.6,-2.4) M3(-4.8,-2.4) M4(-4,-2.4) M5(-3.2,-2.4) M6(-2.4,-2.4) M7(-1.6,-2.4) M8(-0.8,-2.4) M9(0,-2.4) M10(0.8,-2.4) M11(1.6,-2.4) M12(2.4,-2.4) M13(3.2,-2.4) M14(4,-2.4) M15(4.8,-2.4) M16(5.6,-2.4) M17(6.4,-2.4) N1(-6.4,-3.2) N2(-5.6,-3.2) N3(-4.8,-3.2) N4(-4,-3.2) N5(-3.2,-3.2) N6(-2.4,-3.2) N7(-1.6,-3.2) N8(-0.8,-3.2) N9(0,-3.2) N10(0.8,-3.2) N11(1.6,-3.2) N12(2.4,-3.2) N13(3.2,-3.2) N14(4,-3.2) N15(4.8,-3.2) N16(5.6,-3.2) N17(6.4,-3.2) P1(-6.4,-4) P2(-5.6,-4) P3(-4.8,-4) P4(-4,-4) P5(-3.2,-4) P6(-2.4,-4) P7(-1.6,-4) P8(-0.8,-4) P9(0,-4) P10(0.8,-4) P11(1.6,-4) P12(2.4,-4) P13(3.2,-4) P14(4,-4) P15(4.8,-4) P16(5.6,-4) P17(6.4,-4) R1(-6.4,-4.8) R2(-5.6,-4.8) R3(-4.8,-4.8) R4(-4,-4.8) R5(-3.2,-4.8) R6(-2.4,-4.8) R7(-1.6,-4.8) R8(-0.8,-4.8) R9(0,-4.8) R10(0.8,-4.8) R11(1.6,-4.8) R12(2.4,-4.8) R13(3.2,-4.8) R14(4,-4.8) R15(4.8,-4.8) R16(5.6,-4.8) R17(6.4,-4.8) T1(-6.4,-5.6) T2(-5.6,-5.6) T3(-4.8,-5.6) T4(-4,-5.6) T5(-3.2,-5.6) T6(-2.4,-5.6) T7(-1.6,-5.6) T8(-0.8,-5.6) T9(0,-5.6) T10(0.8,-5.6) T11(1.6,-5.6) T12(2.4,-5.6) T13(3.2,-5.6) T14(4,-5.6) T15(4.8,-5.6) T16(5.6,-5.6) T17(6.4,-5.6) U1(-6.4,-6.4) U2(-5.6,-6.4) U3(-4.8,-6.4) U4(-4,-6.4) U5(-3.2,-6.4) U6(-2.4,-6.4) U7(-1.6,-6.4) U8(-0.8,-6.4) U9(0,-6.4) U10(0.8,-6.4) U11(1.6,-6.4) U12(2.4,-6.4) U13(3.2,-6.4) U14(4,-6.4) U15(4.8,-6.4) U16(5.6,-6.4) U17(6.4,-6.4)
  silkscreen extent -7.2,-7.2 7.2,7.2, body extent -7,-7 7,7, height 1.4
"MODULE ATWILC3000-MR110CA" [mm]
  rect 1.88x0.813 smd: 1(-7.31,8.05) 2(-7.31,6.85) 3(-7.31,5.65) 4(-7.31,4.45) 5(-7.31,3.25) 6(-7.31,2.05) 7(-7.31,0.85) 8(-7.31,-0.35) 9(-7.31,-1.55) 10(-7.31,-2.75) 11(-7.31,-3.95) 12(-7.31,-5.15) 13(-7.31,-6.35) 25(7.37,-6.35) 26(7.37,-5.15) 27(7.37,-3.95) 28(7.37,-2.75) 29(7.37,-1.55) 30(7.37,-0.35) 31(7.37,0.85) 32(7.37,2.05) 33(7.37,3.25) 34(7.37,4.45) 35(7.37,5.65) 36(7.37,6.85)
  rect 0.813x1.88 smd: 14(-5.97,-8.33) 15(-4.77,-8.33) 16(-3.57,-8.33) 17(-2.37,-8.33) 18(-1.17,-8.33) 19(0.03,-8.33) 20(1.23,-8.33) 21(2.43,-8.33) 22(3.63,-8.33) 23(4.83,-8.33) 24(6.03,-8.33)
  rect 4.6x4.6 smd: 37(0,0)
  silkscreen extent -7.75,-8.75 7.75,14.25, body extent -7.31,-8.33 7.37,14.05, height 2.73
OSCILLATOR_DSC1001_L3.2W2.5H0.85 [mm] "Oscillator DSC1001"
  rect 0.9x1 smd: 1(-1.05,-0.95) 2(1.05,-0.95) 3(1.05,0.95) 4(-1.05,0.95)
  silkscreen extent -1.7,-1.35 1.7,1.35, body extent -1.6,-1.25 1.6,1.25, height 0.86
OSCILLATOR_DSC60000L2.5W2.0H0.89 [mm]
  rect 0.8x0.7 smd: 1(-0.825,-0.625) 2(0.825,-0.625) 3(0.825,0.625) 4(-0.825,0.625)
  silkscreen extent -1.5,-1.25 1.5,1.25, body extent -1.28,-0.97 1.22,1.03, height 0.82
PLCC-4_CLV1A-FKB [mm] "PLCC4 3 in 1 SMD LED"
  rect 1.5x1.1 smd: 1(-1.5,0.75) 2(-1.5,-0.75) 3(1.5,-0.75) 4(1.5,0.75)
  silkscreen extent -2.5,-1.55 2.5,1.55, body extent -1.75,-1.4 1.75,1.4, height 1.9
QFN-16_3X3_EP1.4X1.4 [mm] "QFN 16 pin P=0.5mm, L=3mm, W=3mm, H=0.9mm"
  oval 0.8x0.3 smd mask+0.05: 1(-1.45,0.75) 2(-1.45,0.25) 3(-1.45,-0.25) 4(-1.45,-0.75) 9(1.45,-0.75) 10(1.45,-0.25) 11(1.45,0.25) 12(1.45,0.75)
  oval 0.3x0.8 smd mask+0.05: 5(-0.75,-1.45) 6(-0.25,-1.45) 7(0.25,-1.45) 8(0.75,-1.45) 13(0.75,1.45) 14(0.25,1.45) 15(-0.25,1.45) 16(-0.75,1.45)
  rect 1.4x1.4 smd: 17(0,0)
  silkscreen extent -1.7,-1.7 1.7,1.7, body extent -1.5,-1.5 1.5,1.5, height 0.9
QFN-32_5X5_EP3.7X3.7 [mm] "QFN32_5MMwith ePAD"
  rrect50% 0.7x0.3 smd mask+0.05: 1(-2.5,1.75) 2(-2.5,1.25) 3(-2.5,0.75) 4(-2.5,0.25) 5(-2.5,-0.25) 6(-2.5,-0.75) 7(-2.5,-1.25) 8(-2.5,-1.75) 17(2.5,-1.75) 18(2.5,-1.25) 19(2.5,-0.75) 20(2.5,-0.25) 21(2.5,0.25) 22(2.5,0.75) 23(2.5,1.25) 24(2.5,1.75)
  rrect50% 0.3x0.7 smd mask+0.05: 9(-1.75,-2.5) 10(-1.25,-2.5) 11(-0.75,-2.5) 12(-0.25,-2.5) 13(0.25,-2.5) 14(0.75,-2.5) 15(1.25,-2.5) 16(1.75,-2.5) 25(1.75,2.5) 26(1.25,2.5) 27(0.75,2.5) 28(0.25,2.5) 29(-0.25,2.5) 30(-0.75,2.5) 31(-1.25,2.5) 32(-1.75,2.5)
  rect 3.7x3.7 smd paste-3.7 mask+0.05: 33(0,0)
  silkscreen extent -2.65,-2.65 2.65,2.68, body extent -2.56,-2.56 2.56,2.56, height 1.01
QFN-36_6x6_EP3.7x3.7 [mm]
  rrect100% 0.9x0.28 smd mask+0.06: 1(-2.75,2) 2(-2.75,1.5) 3(-2.75,1) 4(-2.75,0.5) 5(-2.75,0) 6(-2.75,-0.5) 7(-2.75,-1) 8(-2.75,-1.5) 9(-2.75,-2) 19(2.75,-2) 20(2.75,-1.5) 21(2.75,-1) 22(2.75,-0.5) 23(2.75,0) 24(2.75,0.5) 25(2.75,1) 26(2.75,1.5) 27(2.75,2)
  rrect100% 0.28x0.9 smd mask+0.06: 10(-2,-2.75) 11(-1.5,-2.75) 12(-1,-2.75) 13(-0.5,-2.75) 14(0,-2.75) 15(0.5,-2.75) 16(1,-2.75) 17(1.5,-2.75) 18(2,-2.75) 28(2,2.75) 29(1.5,2.75) 30(1,2.75) 31(0.5,2.75) 32(0,2.75) 33(-0.5,2.75) 34(-1,2.75) 35(-1.5,2.75) 36(-2,2.75)
  rect 3.7x3.7 smd: 37(0,0)
  silkscreen extent -3.1,-3.1 3.1,3.1, body extent -3.1,-3.1 3.1,3.1, height 0.9
QFN-56_8X8_EP5.9X5.9 [mm]
  oval 0.62x0.23 smd mask+0.07: 1(-3.8,3.25) 2(-3.8,2.75) 3(-3.8,2.25) 4(-3.8,1.75) 5(-3.8,1.25) 6(-3.8,0.75) 7(-3.8,0.25) 8(-3.8,-0.25) 9(-3.8,-0.75) 10(-3.8,-1.25) 11(-3.8,-1.75) 12(-3.8,-2.25) 13(-3.8,-2.75) 14(-3.8,-3.25) 29(3.8,-3.25) 30(3.8,-2.75) 31(3.8,-2.25) 32(3.8,-1.75) 33(3.8,-1.25) 34(3.8,-0.75) 35(3.8,-0.25) 36(3.8,0.25) 37(3.8,0.75) 38(3.8,1.25) 39(3.8,1.75) 40(3.8,2.25) 41(3.8,2.75) 42(3.8,3.25)
  oval 0.23x0.62 smd mask+0.07: 15(-3.25,-3.8) 16(-2.75,-3.8) 17(-2.25,-3.8) 18(-1.75,-3.8) 19(-1.25,-3.8) 20(-0.75,-3.8) 21(-0.25,-3.8) 22(0.25,-3.8) 23(0.75,-3.8) 24(1.25,-3.8) 25(1.75,-3.8) 26(2.25,-3.8) 27(2.75,-3.8) 28(3.25,-3.8) 43(3.25,3.8) 44(2.75,3.8) 45(2.25,3.8) 46(1.75,3.8) 47(1.25,3.8) 48(0.75,3.8) 49(0.25,3.8) 50(-0.25,3.8) 51(-0.75,3.8) 52(-1.25,3.8) 53(-1.75,3.8) 54(-2.25,3.8) 55(-2.75,3.8) 56(-3.25,3.8)
  rect 5.9x5.9 smd paste-5.9 mask+0.07: 57(0,0)
  silkscreen extent -4.05,-4 4,4, body extent -4.01,-4.02 4.02,4.01, height 0.95
QFN-64_8X8-EP6.5SQ [mm] "QFN64 8X8 MM PKG 6.5 MM FLAG PAD GANG-MASKED PADS WINDOWED PASTE"
  oval 0.8x0.25 smd mask+0.005: 1(-3.9,3) 2(-3.9,2.6) 3(-3.9,2.2) 4(-3.9,1.8) 5(-3.9,1.4) 6(-3.9,1) 7(-3.9,0.6) 8(-3.9,0.2) 9(-3.9,-0.2) 10(-3.9,-0.6) 11(-3.9,-1) 12(-3.9,-1.4) 13(-3.9,-1.8) 14(-3.9,-2.2) 15(-3.9,-2.6) 16(-3.9,-3) 33(3.9,-3) 34(3.9,-2.6) 35(3.9,-2.2) 36(3.9,-1.8) 37(3.9,-1.4) 38(3.9,-1) 39(3.9,-0.6) 40(3.9,-0.2) 41(3.9,0.2) 42(3.9,0.6) 43(3.9,1) 44(3.9,1.4) 45(3.9,1.8) 46(3.9,2.2) 47(3.9,2.6) 48(3.9,3)
  oval 0.25x0.8 smd mask+0.005: 17(-3,-3.9) 18(-2.6,-3.9) 19(-2.2,-3.9) 20(-1.8,-3.9) 21(-1.4,-3.9) 22(-1,-3.9) 23(-0.6,-3.9) 24(-0.2,-3.9) 25(0.2,-3.9) 26(0.6,-3.9) 27(1,-3.9) 28(1.4,-3.9) 29(1.8,-3.9) 30(2.2,-3.9) 31(2.6,-3.9) 32(3,-3.9) 49(3,3.9) 50(2.6,3.9) 51(2.2,3.9) 52(1.8,3.9) 53(1.4,3.9) 54(1,3.9) 55(0.6,3.9) 56(0.2,3.9) 57(-0.2,3.9) 58(-0.6,3.9) 59(-1,3.9) 60(-1.4,3.9) 61(-1.8,3.9) 62(-2.2,3.9) 63(-2.6,3.9) 64(-3,3.9)
  rect 6.4x6.4 smd paste-6.4 mask+0.051: 65(0,0)
  silkscreen extent -4.57,-4.15 4.15,4.57, body extent -4,-4 4,4, height 1.01
QFN-64_9X9_EP6 [mm] "QFN, 64-Leads, Body 9.00x9.00mm, Pitch 0.50mm, Thermal Pad 6.00x6.00mm, IPC Medium Density"
  oval 0.8x0.3 smd: 1(-4.4,3.75) 2(-4.4,3.25) 3(-4.4,2.75) 4(-4.4,2.25) 5(-4.4,1.75) 6(-4.4,1.25) 7(-4.4,0.75) 8(-4.4,0.25) 9(-4.4,-0.25) 10(-4.4,-0.75) 11(-4.4,-1.25) 12(-4.4,-1.75) 13(-4.4,-2.25) 14(-4.4,-2.75) 15(-4.4,-3.25) 16(-4.4,-3.75) 33(4.4,-3.75) 34(4.4,-3.25) 35(4.4,-2.75) 36(4.4,-2.25) 37(4.4,-1.75) 38(4.4,-1.25) 39(4.4,-0.75) 40(4.4,-0.25) 41(4.4,0.25) 42(4.4,0.75) 43(4.4,1.25) 44(4.4,1.75) 45(4.4,2.25) 46(4.4,2.75) 47(4.4,3.25) 48(4.4,3.75)
  oval 0.3x0.8 smd: 17(-3.75,-4.4) 18(-3.25,-4.4) 19(-2.75,-4.4) 20(-2.25,-4.4) 21(-1.75,-4.4) 22(-1.25,-4.4) 23(-0.75,-4.4) 24(-0.25,-4.4) 25(0.25,-4.4) 26(0.75,-4.4) 27(1.25,-4.4) 28(1.75,-4.4) 29(2.25,-4.4) 30(2.75,-4.4) 31(3.25,-4.4) 32(3.75,-4.4) 49(3.75,4.4) 50(3.25,4.4) 51(2.75,4.4) 52(2.25,4.4) 53(1.75,4.4) 54(1.25,4.4) 55(0.75,4.4) 56(0.25,4.4) 57(-0.25,4.4) 58(-0.75,4.4) 59(-1.25,4.4) 60(-1.75,4.4) 61(-2.25,4.4) 62(-2.75,4.4) 63(-3.25,4.4) 64(-3.75,4.4)
  rect 6x6 smd paste-6 mask+0.051: 65(0,0)
  silkscreen extent -5.01,-4.65 4.65,5.01, body extent -4.5,-4.5 4.5,4.5, height 1.01
RES_C_0201 [mm] "Chip Resistor, 2-Leads, Body 0.6x0.3mm, IPC Medium Density"
  rrect50% 0.275x0.3 smd mask+0.064: 1(-0.262,0) 2(0.262,0)
  body extent -0.3,-0.15 0.3,0.15, height 0.22
RES_C_0402 [mm] "Chip Resistor, 2-Leads, Body 1.0x0.5mm, IPC Medium Density"
  rrect50% 0.55x0.6 smd: 1(-0.45,0) 2(0.45,0)
  body extent -0.5,-0.3 0.5,0.3, height 0.2
RES_C_0603 [mm] "Chip Resistor, 2-Leads, Body 1.6x0.8mm, IPC Medium Density"
  rrect50% 0.8x0.9 smd: 1(-0.8,0) 2(0.8,0)
  silkscreen extent -0.1,-0.38 0.1,0.38, body extent -0.8,-0.4 0.8,0.4, height 0.3
RES_C_0805 [mm] "Chip Resistor, 2-Leads, Body 2.0x1.3mm, IPC Medium Density"
  rrect50% 0.9x1.4 smd: 1(-0.95,0) 2(0.95,0)
  silkscreen extent -0.2,-0.7 0.2,0.7, body extent -1,-0.62 1,0.63, height 0.78
RES_C_1206 [mm] "Chip Resistor, 2-Leads, Body 3.2x1.6mm, IPC Medium Density"
  rrect50% 1x1.75 smd: 1(-1.5,0) 2(1.5,0)
  silkscreen extent -0.6,-0.77 0.6,0.78, body extent -1.6,-0.8 1.6,0.8, height 1
RES_C_1206_SHUNT [mm] "Chip Resistor, 2-Leads, Body 3.2x1.6mm, IPC Medium Density"
  rect 1x0.5 smd mask+0.1: 1(-1.5,-0.6) 1(-1.5,0.6) 2(1.5,-0.6) 2(1.5,0.6)
  rect 1x0.35 smd mask+0.1: 3(-1.5,0) 4(1.5,0)
  silkscreen extent -0.6,-0.77 0.6,0.78, body extent -1.6,-0.8 1.6,0.8, height 1
RES_C_CAV_0603x4 [mm]
  rect 0.9x0.65 smd mask+0.025: 1(-0.9,1.2) 2(-0.9,0.4) 3(-0.9,-0.4) 4(-0.9,-1.2) 5(0.9,-1.2) 6(0.9,-0.4) 7(0.9,0.4) 8(0.9,1.2)
  silkscreen extent -1.65,-1.83 1.65,1.83, body extent -0.92,-1.68 0.92,1.68, height 0.7
SC-70-6 [mm]
  rect 0.45x0.95 smd: 1(-0.65,-1.1) 2(0,-1.1) 3(0.65,-1.1) 4(0.65,1.1) 5(0,1.1) 6(-0.65,1.1)
  silkscreen extent -1,-0.33 1,0.33, body extent -1,-1.05 1,1.05, height 0.92
"SiA923AEDJ PPAK_SC70_6L" [mm] "6-Leads SC70 Dual pad, 2.05mm x 2.05mm package"
  rect 0.325x0.3 smd mask+0.05: 1(-0.913,0.65) 2(-0.913,0) 3(-0.913,-0.65) 4(0.913,-0.65) 5(0.913,0) 6(0.913,0.65)
  rect 0.95x0.613 smd mask+0.05: 7(0,0.455) 8(0,-0.455)
  silkscreen extent -1.38,-1.1 1.38,1.1, body extent -1.02,-1.02 1.02,1.02, height 0.8
SOCKET_mikroBUS_F_2.54_2x8_V_25.4x21 [mil]
  rect 60x60 hole 35.43: 1(-450,350)
  round 60 hole 35.43: 2(-450,250) 3(-450,150) 4(-450,50) 5(-450,-50) 6(-450,-150) 7(-450,-250) 8(-450,-350) 9(450,-350) 10(450,-250) 11(450,-150) 12(450,-50) 13(450,50) 14(450,150) 15(450,250) 16(450,350)
  silkscreen extent -550,-550 550,588, body extent -495,-410 498,410, height 335
SOD-123 [mm] "Diode SOD-123 Body L=2.85, W= 1.8"
  rect 0.9x1.2 smd: 1(-1.7,0) 2(1.7,0)
  silkscreen extent -1.87,-1.05 2.02,1.05, body extent -1.92,-0.85 1.93,0.85, height 1.43
SOD-123FL [mm]
  rect 1.5x1.3 smd: 1(-1.6,0) 2(1.6,0)
  silkscreen extent -2.2,-1.15 2.45,1.15, body extent -1.79,-0.82 1.79,0.83, height 0.94
SOD-323 [mm] "Molded Diode, 2-Leads, Body 1.8x1.4mm, IPC Medium Density"
  rect 0.63x0.83 smd: 1(-1.115,0) 2(1.115,0)
  silkscreen extent -0.17,-0.7 1.73,0.7, body extent -1.3,-0.67 1.3,0.68, height 1.1
SOIC-8 [mm] "SOIC, 8-Leads, Overall 4.9x6mm, Pitch 1.27mm, IPC Medium Density"
  oval 1.55x0.6 smd: 1(-2.7,1.905) 2(-2.7,0.635) 3(-2.7,-0.635) 4(-2.7,-1.905) 5(2.7,-1.905) 6(2.7,-0.635) 7(2.7,0.635) 8(2.7,1.905)
  silkscreen extent -1.6,-2.5 1.6,2.5, body extent -3.01,-2.5 3.01,2.5, height 1.75
SOIC-8_150MIL [mm] "SOIC-8 Narrow"
  oval 2.1x0.6 smd: 1(-2.425,1.905) 2(-2.425,0.635) 3(-2.425,-0.635) 4(-2.425,-1.905) 5(2.425,-1.905) 6(2.425,-0.635) 7(2.425,0.635) 8(2.425,1.905)
  silkscreen extent -0.97,-2.45 0.98,2.45, body extent -2.96,-2.5 3.06,2.5, height 1.75
SOIJ-8 [mm] "SOIC, 8-Leads, Overall 4.9x6mm, Pitch 1.27mm, IPC Medium Density"
  oval 1.55x0.6 smd: 1(-3.65,1.905) 2(-3.65,0.635) 3(-3.65,-0.635) 4(-3.65,-1.905) 5(3.65,-1.905) 6(3.65,-0.635) 7(3.65,0.635) 8(3.65,1.905)
  silkscreen extent -2.5,-2.8 2.5,2.8, body extent -4.05,-2.73 4.05,2.73, height 1.75
SOT-23-3 [mm]
  rect 0.65x1.05 smd: 1(-0.95,-1.15) 2(0.95,-1.15) 3(0,1.15)
  silkscreen extent -1.6,-0.75 1.6,0.72, body extent -1.5,-1.25 1.5,1.25, height 1.09
SOT-23-5 [mm] "SOT-23-5"
  rect 0.55x1.3 smd: 1(-0.95,-1.2) 2(0,-1.2) 3(0.95,-1.2) 4(0.95,1.2) 5(-0.95,1.2)
  silkscreen extent -1.35,-0.25 1.35,0.25, body extent -1.5,-1.25 1.5,1.25, height 1.08
SOT-23-6 [mm] "SOT-23-6"
  rect 0.55x1.15 smd: 1(-0.95,-1.4) 2(0,-1.4) 3(0.95,-1.4) 4(0.95,1.4) 5(0,1.4) 6(-0.95,1.4)
  silkscreen extent -1.55,-0.53 1.55,0.53, body extent -1.5,-1.48 1.5,1.52, height 1.5
SOT-353 [mm]
  rect 0.42x0.65 smd paste+0: 1(-0.65,-0.98)
  rect 0.42x0.65 smd: 2(0,-0.98) 3(0.65,-0.98) 4(0.65,0.98) 5(-0.65,0.98)
  silkscreen extent -1.3,-0.6 1.3,0.6, body extent -1.1,-1.2 1.1,1.2, height 1.1
SW_SMD_6mmX6mm_TL3301 [mm]
  rect 2.5x1.4 smd: 1(-4.55,2.25) 2(4.55,2.25) 3(-4.55,-2.25) 4(4.55,-2.25)
  silkscreen extent -3,-3 3,3, body extent -5,-3 5,3, height 5.12
TFBGA-96_13X7.5 [mm]
  round 0.4 smd mask+0.05: A1(-3.2,6) A2(-2.4,6) A3(-1.6,6) A7(1.6,6) A8(2.4,6) A9(3.2,6) B1(-3.2,5.2) B2(-2.4,5.2) B3(-1.6,5.2) B7(1.6,5.2) B8(2.4,5.2) B9(3.2,5.2) C1(-3.2,4.4) C2(-2.4,4.4) C3(-1.6,4.4) C7(1.6,4.4) C8(2.4,4.4) C9(3.2,4.4) D1(-3.2,3.6) D2(-2.4,3.6) D3(-1.6,3.6) D7(1.6,3.6) D8(2.4,3.6) D9(3.2,3.6) E1(-3.2,2.8) E2(-2.4,2.8) E3(-1.6,2.8) E7(1.6,2.8) E8(2.4,2.8) E9(3.2,2.8) F1(-3.2,2) F2(-2.4,2) F3(-1.6,2) F7(1.6,2) F8(2.4,2) F9(3.2,2) G1(-3.2,1.2) G2(-2.4,1.2) G3(-1.6,1.2) G7(1.6,1.2) G8(2.4,1.2) G9(3.2,1.2) H1(-3.2,0.4) H2(-2.4,0.4) H3(-1.6,0.4) H7(1.6,0.4) H8(2.4,0.4) H9(3.2,0.4) J1(-3.2,-0.4) J2(-2.4,-0.4) J3(-1.6,-0.4) J7(1.6,-0.4) J8(2.4,-0.4) J9(3.2,-0.4) K1(-3.2,-1.2) K2(-2.4,-1.2) K3(-1.6,-1.2) K7(1.6,-1.2) K8(2.4,-1.2) K9(3.2,-1.2) L1(-3.2,-2) L2(-2.4,-2) L3(-1.6,-2) L7(1.6,-2) L8(2.4,-2) L9(3.2,-2) M1(-3.2,-2.8) M2(-2.4,-2.8) M3(-1.6,-2.8) M7(1.6,-2.8) M8(2.4,-2.8) M9(3.2,-2.8) N1(-3.2,-3.6) N2(-2.4,-3.6) N3(-1.6,-3.6) N7(1.6,-3.6) N8(2.4,-3.6) N9(3.2,-3.6) P1(-3.2,-4.4) P2(-2.4,-4.4) P3(-1.6,-4.4) P7(1.6,-4.4) P8(2.4,-4.4) P9(3.2,-4.4) R1(-3.2,-5.2) R2(-2.4,-5.2) R3(-1.6,-5.2) R7(1.6,-5.2) R8(2.4,-5.2) R9(3.2,-5.2) T1(-3.2,-6) T2(-2.4,-6) T3(-1.6,-6) T7(1.6,-6) T8(2.4,-6) T9(3.2,-6)
  silkscreen extent -3.9,-6.6 3.9,6.6, body extent -3.75,-6.5 3.75,6.5, height 1.13
TFBGA-100_P0.8_9X9X1.1 [mm]
  round 0.4 smd: A1(-3.6,3.6) A2(-2.8,3.6) A3(-2,3.6) A4(-1.2,3.6) A5(-0.4,3.6) A6(0.4,3.6) A7(1.2,3.6) A8(2,3.6) A9(2.8,3.6) A10(3.6,3.6) B1(-3.6,2.8) B2(-2.8,2.8) B3(-2,2.8) B4(-1.2,2.8) B5(-0.4,2.8) B6(0.4,2.8) B7(1.2,2.8) B8(2,2.8) B9(2.8,2.8) B10(3.6,2.8) C1(-3.6,2) C2(-2.8,2) C3(-2,2) C4(-1.2,2) C5(-0.4,2) C6(0.4,2) C7(1.2,2) C8(2,2) C9(2.8,2) C10(3.6,2) D1(-3.6,1.2) D2(-2.8,1.2) D3(-2,1.2) D4(-1.2,1.2) D5(-0.4,1.2) D6(0.4,1.2) D7(1.2,1.2) D8(2,1.2) D9(2.8,1.2) D10(3.6,1.2) E1(-3.6,0.4) E2(-2.8,0.4) E3(-2,0.4) E4(-1.2,0.4) E5(-0.4,0.4) E6(0.4,0.4) E7(1.2,0.4) E8(2,0.4) E9(2.8,0.4) E10(3.6,0.4) F1(-3.6,-0.4) F2(-2.8,-0.4) F3(-2,-0.4) F4(-1.2,-0.4) F5(-0.4,-0.4) F6(0.4,-0.4) F7(1.2,-0.4) F8(2,-0.4) F9(2.8,-0.4) F10(3.6,-0.4) G1(-3.6,-1.2) G2(-2.8,-1.2) G3(-2,-1.2) G4(-1.2,-1.2) G5(-0.4,-1.2) G6(0.4,-1.2) G7(1.2,-1.2) G8(2,-1.2) G9(2.8,-1.2) G10(3.6,-1.2) H1(-3.6,-2) H2(-2.8,-2) H3(-2,-2) H4(-1.2,-2) H5(-0.4,-2) H6(0.4,-2) H7(1.2,-2) H8(2,-2) H9(2.8,-2) H10(3.6,-2) J1(-3.6,-2.8) J2(-2.8,-2.8) J3(-2,-2.8) J4(-1.2,-2.8) J5(-0.4,-2.8) J6(0.4,-2.8) J7(1.2,-2.8) J8(2,-2.8) J9(2.8,-2.8) J10(3.6,-2.8) K1(-3.6,-3.6) K2(-2.8,-3.6) K3(-2,-3.6) K4(-1.2,-3.6) K5(-0.4,-3.6) K6(0.4,-3.6) K7(1.2,-3.6) K8(2,-3.6) K9(2.8,-3.6) K10(3.6,-3.6)
  silkscreen extent -4.7,-4.7 4.7,4.7, body extent -4.5,-4.5 4.5,4.5, height 1.05
ULLGA-6_1X1 [mm]
  rect 0.22x0.53 smd mask+0.11: 1(-0.35,-0.325)
  rect 0.22x0.48 smd mask+0.11: 2(0,-0.35) 3(0.35,-0.35) 4(0.35,0.35) 5(0,0.35) 6(-0.35,0.35)
  silkscreen extent -0.77,-0.9 0.77,0.9, body extent -0.5,-0.52 0.5,0.53, height 0.46
US-8 [mm] "VFSOP-8, US-8, 0.5mm Pitch"
  oval 1.25x0.3 smd: 1(-1.325,0.75) 2(-1.325,0.25) 3(-1.325,-0.25) 4(-1.325,-0.75) 5(1.325,-0.75) 6(1.325,-0.25) 7(1.325,0.25) 8(1.325,0.75)
  silkscreen extent -1.38,-1.05 0.4,1.51, body extent -1.7,-1 1.7,1, height 0.68
WLCSP-16_2.215X2.16 [mm] "Microchip Technology Drawing C04-6036A"
  oval 0.2x0.25 smd mask+0.05: A1(-0.75,0.75) A2(-0.25,0.75) D1(-0.75,-0.75) D2(-0.25,-0.75)
  round 0.25 smd mask+0.05: A3(0.25,0.75) A4(0.75,0.75) B1(-0.75,0.25) B2(-0.25,0.25) B3(0.25,0.25) C1(-0.75,-0.25) C2(-0.25,-0.25) C3(0.25,-0.25) D3(0.25,-0.75)
  oval 0.25x0.2 smd mask+0.05: B4(0.75,0.25) C4(0.75,-0.25) D4(0.75,-0.75)
  silkscreen extent -1.25,-1.22 1.25,1.22, body extent -1.1,-1.05 1.1,1.05, height 0.64

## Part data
C1 C146 C157 C158 C159 C226 C227 C236 C286: library part CAP0265, "Capacitor", Manufacturer 1=AVX, Manufacturer 2=Murata, Manufacturer 4=Panasonic, Manufacturer 5=TDK, Manufacturer 6="Taiyo Yuden", Manufacturer Part Number 1=0603YD105KAT2A, Manufacturer Part Number 2=GRM188R61C105KA93D, Manufacturer Part Number 3=GRM185R61C105KE44D, Manufacturer Part Number 4=ECJ-1VB1C105K, Manufacturer Part Number 5=C1608X5R1C105K, Manufacturer Part Number 6=EMK107BJ105KA-T, Operating Temperature="-55C to +85C", Package=0603, Supplier Part Number 1=478-1249-1-ND, Temperature Coeffcient=X5R, Tolerance=10%, Voltage=16V
C2 C4 C6 C7 C19 C21 C24 C25 C26 C28 C52 C58 C59 C68 C76 C77 C78 C79 C80 C81 C82 C83 C84 C85 C86 C88 C89 C90 C91 C92 C93 C94 C95 C96 C97 C98 C101 C102 C103 C104 C105 C106 C107 C108 C109 C110 C111 C112 C113 C114 C115 C117 C118 C119 C120 C121 C122 C123 C126 C127 C128 C129 C130 C131 C132 C133 C134 C135 C144 C145 C148 C149 C153 C154 C155 C156 C167 C182 C184 C190 C191 C192 C193 C194 C195 C196 C197 C198 C199 C200 C201 C202 C203 C204 C205 C206 C207 C208 C209 C210 C211 C212 C213 C214 C215 C216 C217 C218 C219 C220 C221 C223 C224 C225 C228 C230 C231 C232 C233 C234 C235 C237 C238 C239 C241 C250 C256 C257 C259 C260 C261 C262 C264 C265 C266 C267 C268 C269 C270 C271 C272 C273 C274 C275 C276 C277 C287 C288 C289 C291 C292 C293 C294: library part CAP1033, "Capacitor", Manufacturer 1=Murata, Manufacturer Part Number 1=GRM155R71C104KA88D, Operating Temperature="-55C to +125C", Package=0402, Supplier Part Number 1=490-3261-2-ND, Temperature Coeffcient=X7R, Tolerance=10%, Voltage=16V
C3 C8 C9 C10 C20 C22 C75 C87 C99 C100: library part CAP1468, "Capacitor", Manufacturer 1="TDK Corporation", Manufacturer 2="Murata Electronics North America", Manufacturer Part Number 1=C1005X7S1A225K050BC, Manufacturer Part Number 2=GRM155C71A225KE11J, Operating Temperature="-55C to +125C", Package=0402, Supplier Part Number 1=445-9097-1-ND, Temperature Coeffcient=X7S, Tolerance=10%, Voltage=10V
C5: library part CAP1487, "Capacitor", Manufacturer 1="Elna America", Manufacturer Part Number 1=DSK-3R3H224U-HL, Operating Temperature="-10C to +60C", Package=P4.6D4.8H1.66, Supplier Part Number 1=604-1020-1-ND, Tolerance="-20%, +80%", Voltage=3.3V
C11 C13 C15 C17 C23 C57 C62 C69 C71: library part CAP1684, "Capacitor", Manufacturer 1="TDK Corporation", Manufacturer Part Number 1=C1005X5R1A475K050BC, Operating Temperature="-55C to 85C", Package=0402, Supplier Part Number 1=445-13820-1-ND, Temperature Coeffcient=X5R, Tolerance=10%, Voltage=10V
C12 C14 C16 C18: library part CAP1645, "Capacitor", Manufacturer 1="Taiyo Yuden", Manufacturer Part Number 1=LMK212BJ226MG-T, Operating Temperature="-55C to +85C", Package=0805, Supplier Part Number 1=587-1958-1-ND, Temperature Coeffcient=X5R, Tolerance=20%, Voltage=10V
C27: library part CAP1452, "Capacitor", Manufacturer 1="TDK Corporation", Manufacturer Part Number 1=C0603C0G1E220K030BA, Operating Temperature="-55C to +125C", Package=0201, Supplier Part Number 1=445-13594-2-ND, Temperature Coeffcient=NP0, Tolerance=10%, Voltage=25V
C29 C30 C32: library part CAP1323, "Capacitor", Manufacturer 1="Taiyo Yuden", Manufacturer Part Number 1=EMK212BB7106MG-T, Operating Temperature="-55C to +125C", Package=0805, Supplier Part Number 1=587-3319-1-ND, Temperature Coeffcient=X7R, Tolerance=20%, Voltage=16V
C31 C33 C34 C35 C36 C37 C38 C39 C40 C41 C42 C43 C44 C45 C46 C47 C48 C49 C50 C53 C54 C55 C56 C61 C64 C65 C66 C70 C72 C73: library part CAP1559, "Capacitor", Manufacturer 1="Murata Electronics North America", Manufacturer Part Number 1=GRM033R61C104KE84D, Operating Temperature="-55°C to 85°C", Package=0201, Supplier Part Number 1=490-9985-2-ND, Temperature Coeffcient=X5R, Tolerance=10%, Voltage=16V
C51 C60 C67 C299: library part CAP1091, "Capacitor", Manufacturer 1=Murata, Manufacturer Part Number 1=GRM1555C1H180JA01D, Manufacturer Part Number 2=GRM1555C1H180JZ01, Operating Temperature="-55C to +125C", Package=0402, Supplier Part Number 1=490-5858-1-ND, Temperature Coeffcient=C0G, Tolerance=5%, Voltage=50V
C63 C152 C183 C189 C222 C229: library part CAP1042, "Capacitor", Manufacturer 1=Murata, Manufacturer 2="Murata Electronics North America", Manufacturer 3="Panasonic Electronic Components", Manufacturer Part Number 1=GRM1555C1H220JZ01D, Manufacturer Part Number 2=GRM1555C1H220JA01D, Manufacturer Part Number 3=ECJ-0EC1H220J, Operating Temperature="-55C to +125C", Package=0402, Supplier Part Number 1=490-1283-2-ND, Temperature Coeffcient=NP0, Tolerance=5%, Voltage=50V
C74: library part CAP1453, "Capacitor", Manufacturer 1="TDK Corporation", Manufacturer Part Number 1=C0603C0G1E100D030BA, Operating Temperature="-55C to +125C", Package=0201, Supplier Part Number 1=445-4651-2-ND, Temperature Coeffcient=C0G, Tolerance=0.5pF, Voltage=25V
C116 C163: library part CAP1323, "Capacitor", Manufacturer 1="Taiyo Yuden", Manufacturer Part Number 1=EMK212BB7106MG-T, Operating Temperature="-55C to +125C", Package=0805, Supplier Part Number 1=587-3319-1-ND, Temperature Coeffcient=X7R, Tolerance=20%, Voltage=16
C124 C125: library part CAP0121, "Capacitor", Manufacturer 1=TDK, Manufacturer 2=Yageo, Manufacturer 3=Panasonic, Manufacturer Part Number 1=C1608C0G1H150J, Manufacturer Part Number 2=CC0603JRNP09BN150, Manufacturer Part Number 3=ECJ-1VC1H150J, Operating Temperature="-55C to +125C", Package=0603, Supplier Part Number 1=445-1271-1-ND, Temperature Coeffcient=NP0, Tolerance=5%, Voltage=50V
C136 C137 C138 C139 C140 C141: library part CAP1112, "Capacitor", Manufacturer 1=KEMET, Manufacturer Part Number 1=C0603C101J1GACTU, Operating Temperature="-55C to +125C", Package=0603, Supplier Part Number 1=C0603C101J1GACTU-ND, Temperature Coeffcient="C0G, NP0", Tolerance=5%, Voltage=100V
C142 C143: library part CAP1272, "Capacitor", Manufacturer 1="TDK Corporation", Manufacturer Part Number 1=C2012X7R2A472K085AE, Manufacturer Part Number 2=C2012X7R2A472K, Operating Temperature="-55C to +125C", Package=0805, Supplier Part Number 1=445-173661-1-ND, Temperature Coeffcient=X7R, Tolerance=10%, Voltage=100V
C147 C150 C151 C160 C185 C186 C187 C188 C281: library part CAP1648, "Capacitor", Manufacturer 1="TDK Corporation", Manufacturer Part Number 1=C1608X5R1A226M080AC, Operating Temperature="-55C to +85C", Package=0603, Supplier Part Number 1=2525091, Temperature Coeffcient=X5R, Tolerance=20%, Voltage=10V
C161 C168 C169 C170 C171 C172 C173 C174 C175 C176 C177 C178 C179 C180 C245 C247 C249 C280: library part CAP0611, "Capacitor", Manufacturer 1=Murata, Manufacturer Part Number 1=GRM155R71C103KA01D, Operating Temperature="-55C to +125C", Package=0402, Supplier Part Number 1=490-1313-1-ND, Temperature Coeffcient=X7R, Tolerance=10%, Voltage=16V
C162 C164 C165 C166 C240 C242 C244 C246 C255: library part CAP0613, "Capacitor", Manufacturer 1=Murata, Manufacturer Part Number 1=GRM1555C1H100JZ01D, Manufacturer Part Number 2=GJM1555C1H100JB01D, Manufacturer Part Number 3=GRM1555C1H100JA01D, Operating Temperature="-55C to +125C", Package=0402, Supplier Part Number 1=490-1278-1-ND, Temperature Coeffcient=NP0, Tolerance=5%, Voltage=50V
C181 C248: library part CAP1058, "Capacitor", Manufacturer 1=TDK, Manufacturer Part Number 1=C1608X7R1H223K, Operating Temperature="-55C to +125C", Package=0603, Supplier Part Number 1=445-1312-1-ND, Temperature Coeffcient=X7R, Tolerance=10%, Voltage=50V
C251 C254: library part CAP1071, "Capacitor", Manufacturer 1=Yageo, Manufacturer Part Number 1=CC0402KRX7R9BB103, Operating Temperature="-55C to +125C", Package=0402, Supplier Part Number 1=311-1349-2-ND, Temperature Coeffcient=X7R, Tolerance=10%, Voltage=50V
C252 C253: library part CAP0559, "Capacitor", Manufacturer 1=Murata, Manufacturer Part Number 1=GRM188R71A225KE15D, Operating Temperature="-55C to +125C", Package=0603, Supplier Part Number 1=490-4520-1-ND, Temperature Coeffcient=X7R, Tolerance=10%, Voltage=10V
C258 C263: library part CAP1288, "Capacitor", Manufacturer 1="TDK Corporation", Manufacturer Part Number 1=C1608X5R1C475K080AC, Operating Temperature="-55C to +85C", Package=0603, Supplier Part Number 1=445-7478-1-ND, Temperature Coeffcient=X5R, Tolerance=10%, Voltage=16V
C278 C301: library part CAP1463, "Capacitor", Manufacturer 1="TDK Corporation", Manufacturer Part Number 1=C1005X7R1H104K050BB, Operating Temperature="-55C to +125C", Package=0402, Supplier Part Number 1=445-5932-1-ND, Temperature Coeffcient=X7R, Tolerance=10%, Voltage=50V
C279 C300: library part CAP1331, "Capacitor", Manufacturer 1="TDK Corporation", Manufacturer Part Number 1=C3216X5R1C476M160AB, Operating Temperature="-55C to +85C", Package=1206, Supplier Part Number 1=445-6003-1-ND, Temperature Coeffcient=X5R, Tolerance=20%, Voltage=16V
